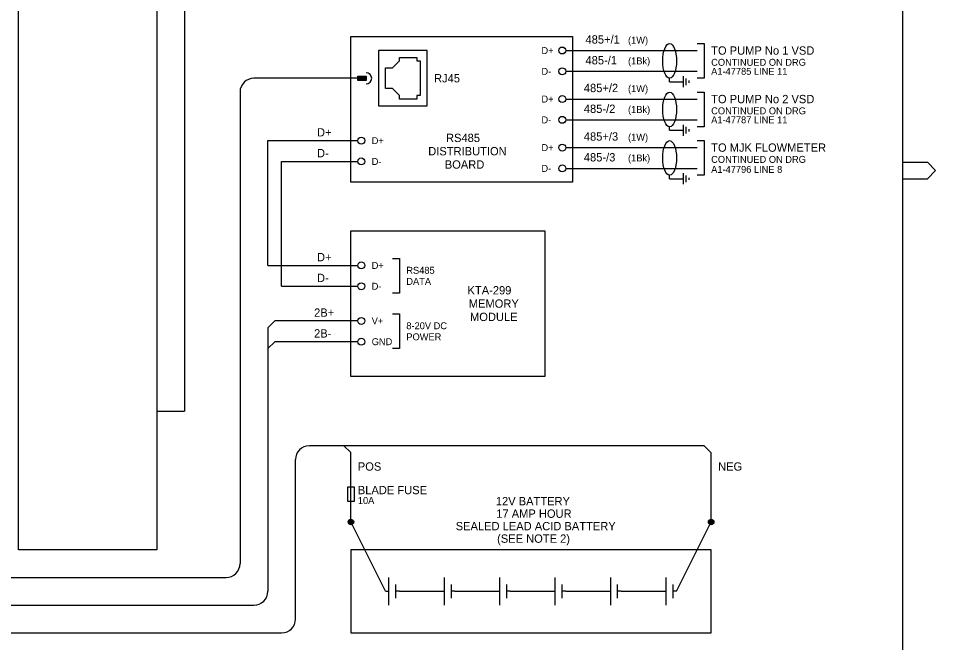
# Model space of a CAD drawing. Extents: x 0 to 841, y 0 to 594.
# Drawn here: x 510 to 841, y 126.5 to 351.6 of the extents above; entities that cross this region are included whole.
import ezdxf

# ---------------------------------------------------------------- set-up
doc = ezdxf.new("R2010")
doc.units = 0
for name, color, linetype in [('A1BORDER', 7, 'Continuous'), ('Level 1', 7, 'Continuous'), ('Level 10', 7, 'Continuous')]:
    doc.layers.add(name, color=color, linetype=linetype)

msp = doc.modelspace()

# ---------------------------------------------------------------- linework, layer by layer
at = {"layer": 'A1BORDER'}
for p, q in [((829, 581), (829, 15)), ((829, 299.76), (838, 299.76)), ((838, 299.76), (841, 296.76)), ((838, 293.76), (841, 296.76)), ((829, 293.76), (838, 293.76))]:
    msp.add_line(p, q, dxfattribs=at)
at = {"layer": 'Level 1'}
for p, q in [((570, 430), (570, 210)), ((707.5, 340), (755, 340)), ((647.5, 336.25), (645, 333.75)), ((647.5, 336.25), (647.5, 337.5)), ((647.5, 337.5), (653.75, 337.5)), ((653.75, 337.5), (653.75, 336.25)), ((653.75, 336.25), (655, 336.25)), ((655, 336.25), (655, 323.75)), ((642.5, 326.25), (642.5, 333.75)), ((642.5, 333.75), (645, 333.75)), ((707.5, 332.5), (755, 332.5)), ((632.5, 330), (595, 330)), ((745, 328.75), (745, 330)), ((745, 328.75), (750, 328.75)), ((590, 325), (590, 155)), ((645, 326.25), (642.5, 326.25)), ((647.5, 323.75), (645, 326.25)), ((647.5, 322.5), (647.5, 323.75)), ((653.75, 322.5), (647.5, 322.5)), ((655, 323.75), (653.75, 323.75)), ((653.75, 323.75), (653.75, 322.5)), ((707.5, 322.5), (755, 322.5)), ((707.5, 315), (755, 315)), ((745, 311.25), (745, 312.5)), ((745, 311.25), (750, 311.25)), ((600, 262.5), (600, 307.5)), ((600, 307.5), (632.5, 307.5)), ((707.5, 305), (755, 305)), ((605, 255), (605, 300)), ((605, 300), (632.5, 300)), ((707.5, 297.5), (755, 297.5)), ((745, 293.75), (745, 295)), ((745, 293.75), (750, 293.75)), ((600, 262.5), (632.5, 262.5)), ((605, 255), (632.5, 255)), ((602.5, 242.5), (600, 240)), ((632.5, 242.5), (602.5, 242.5)), ((600, 240), (600, 145)), ((602.5, 235), (600, 232.5)), ((632.5, 235), (602.5, 235)), ((560, 210), (570, 210)), ((757.5, 197.47), (615, 197.47)), ((630, 195), (627.5, 197.5)), ((757.5, 197.47), (760, 194.97)), ((610, 135), (610, 192.47)), ((630, 170), (630, 195)), ((760, 170), (760, 195)), ((642.5, 145), (630, 170)), ((747.5, 145), (760, 170)), ((385, 150), (585, 150)), ((647.5, 145), (662.5, 145)), ((667.5, 145), (682.5, 145)), ((687.5, 145), (702.5, 145)), ((707.5, 145), (722.5, 145)), ((727.5, 145), (742.5, 145)), ((275, 140), (595, 140)), ((265, 130), (605, 130))]:
    msp.add_line(p, q, dxfattribs=at)
for points in [[(510, 510), (560, 510), (560, 160), (510, 160)], [(630, 345), (710, 345), (710, 292.5), (630, 292.5)], [(657.5, 340), (640, 340), (640, 320), (657.5, 320)], [(630, 275), (700, 275), (700, 222.5), (630, 222.5)], [(760, 130), (760, 160), (630, 160), (630, 130)]]:
    msp.add_lwpolyline(points, close=True, dxfattribs=at)
for points in [[(755, 342.5), (757.5, 342.5), (757.5, 330), (755, 330)], [(755, 325), (757.5, 325), (757.5, 312.5), (755, 312.5)], [(755, 307.5), (757.5, 307.5), (757.5, 295), (755, 295)], [(645, 265), (647.5, 265), (647.5, 252.5), (645, 252.5)], [(645, 245), (647.5, 245), (647.5, 232.5), (645, 232.5)]]:
    msp.add_lwpolyline(points, dxfattribs=at)
for centre, start, end in [((595, 325), 90, 180), ((615, 192.47), 90, 180), ((585, 155), 270, 360), ((595, 145), 270, 360), ((605, 135), 270, 0)]:
    msp.add_arc(centre, 5, start, end, dxfattribs=at)
for centre in [(745, 336.25), (745, 318.75), (745, 301.25)]:
    msp.add_ellipse(centre, major_axis=(0, 6.25), ratio=0.4, dxfattribs=at)
at = {"layer": 'Level 10'}
for p, q in [((635.5, 330.48), (632.5, 330.48)), ((635.5, 330.18), (632.5, 330.18)), ((635.5, 329.88), (632.5, 329.88)), ((635.5, 329.58), (632.5, 329.58)), ((635.5, 329.28), (632.5, 329.28)), ((750, 326.75), (750, 330.75)), ((751, 327.55), (751, 329.95)), ((752, 328.35), (752, 329.15)), ((750, 309.25), (750, 313.25)), ((751, 310.05), (751, 312.45)), ((752, 310.85), (752, 311.65)), ((750, 291.75), (750, 295.75)), ((751, 292.55), (751, 294.95)), ((752, 293.35), (752, 294.15)), ((629, 170), (629, 170)), ((629.3, 169.29), (629.3, 170.71)), ((629.6, 169.08), (629.6, 170.92)), ((629.9, 169.01), (629.9, 170.99)), ((630.2, 169.02), (630.2, 170.98)), ((630.5, 169.13), (630.5, 170.87)), ((630.8, 169.4), (630.8, 170.6)), ((759, 170), (759, 170)), ((759.3, 169.29), (759.3, 170.71)), ((759.6, 169.08), (759.6, 170.92)), ((759.9, 169.01), (759.9, 170.99)), ((760.2, 169.02), (760.2, 170.98)), ((760.5, 169.13), (760.5, 170.87)), ((760.8, 169.4), (760.8, 170.6)), ((643.74, 140), (643.74, 150)), ((663.74, 140), (663.74, 150)), ((683.74, 140), (683.74, 150)), ((703.74, 140), (703.74, 150)), ((723.74, 140), (723.74, 150)), ((743.74, 140), (743.74, 150)), ((646.24, 142.5), (646.24, 147.5)), ((666.24, 142.5), (666.24, 147.5)), ((686.24, 142.5), (686.24, 147.5)), ((706.24, 142.5), (706.24, 147.5)), ((726.24, 142.5), (726.24, 147.5)), ((746.24, 142.5), (746.24, 147.5)), ((642.5, 145), (643.74, 145)), ((647.5, 145), (646.24, 145)), ((662.5, 145), (663.74, 145)), ((667.5, 145), (666.24, 145)), ((682.5, 145), (683.74, 145)), ((687.5, 145), (686.24, 145)), ((702.5, 145), (703.74, 145)), ((707.5, 145), (706.24, 145)), ((722.5, 145), (723.74, 145)), ((727.5, 145), (726.24, 145)), ((742.5, 145), (743.74, 145)), ((747.5, 145), (746.24, 145))]:
    msp.add_line(p, q, dxfattribs=at)
msp.add_lwpolyline([(635.5, 329.25), (632.5, 329.25), (632.5, 330.75), (635.5, 330.75)], close=True, dxfattribs=at)
msp.add_lwpolyline([(630, 177.5), (631.25, 177.5), (631.25, 182.5), (628.75, 182.5), (628.75, 177.5), (630, 177.5)], dxfattribs=at)
for centre, radius in [((706.25, 340), 1.25), ((706.25, 332.5), 1.25), ((706.25, 322.5), 1.25), ((706.25, 315), 1.25), ((633.75, 307.5), 1.25), ((706.25, 305), 1.25), ((633.75, 300), 1.25), ((706.25, 297.5), 1.25), ((633.75, 262.5), 1.25), ((633.75, 255), 1.25), ((633.75, 242.5), 1.25), ((633.75, 235), 1.25), ((630, 170), 1), ((760, 170), 1)]:
    msp.add_circle(centre, radius, dxfattribs=at)
msp.add_arc((635.5, 330), 2, 270, 90, dxfattribs=at)

# ---------------------------------------------------------------- texts
at = {"layer": 'Level 1'}
for s, height, p in [('485+/1', 3, (714.65, 342.5)), ('(1W)', 2.5, (730, 342.5)), ('D+', 2.5, (698.76, 338.75)), ('TO PUMP No 1 VSD', 3, (760, 338.5)), ('485-/1', 3, (714.65, 335)), ('(1Bk)', 2.5, (730, 335)), ('CONTINUED ON DRG', 2.5, (760, 334.5)), ('RJ45', 3, (660, 328.5)), ('D-', 2.5, (698.76, 331.25)), ('A1-47785 LINE 11', 2.5, (760, 331.25)), ('485+/2', 3, (714.05, 325)), ('(1W)', 2.5, (730, 325)), ('D+', 2.5, (698.76, 321.25)), ('TO PUMP No 2 VSD', 3, (760, 321)), ('485-/2', 3, (714.05, 317.5)), ('(1Bk)', 2.5, (730, 317.5)), ('CONTINUED ON DRG', 2.5, (760, 317)), ('D-', 2.5, (698.76, 313.75)), ('A1-47787 LINE 11', 2.5, (760, 313.75)), ('D+', 3, (617.76, 309)), ('D+', 2.5, (637.5, 306.25)), ('RS485', 3, (664.32, 307)), ('485+/3', 3, (714.05, 307.5)), ('(1W)', 2.5, (730, 307.5)), ('DISTRIBUTION', 3, (657.9, 302.2)), ('D+', 2.5, (698.76, 303.75)), ('TO MJK FLOWMETER', 3, (760, 303.5)), ('D-', 3, (617.76, 301.5)), ('D-', 2.5, (637.5, 298.75)), ('485-/3', 3, (714.05, 300)), ('(1Bk)', 2.5, (730, 300)), ('CONTINUED ON DRG', 2.5, (760, 299.5)), ('BOARD', 3, (663.87, 297.4)), ('D-', 2.5, (698.76, 296.25)), ('A1-47796 LINE 8', 2.5, (760, 295.88)), ('D+', 3, (617.76, 264)), ('D+', 2.5, (637.5, 261.25)), ('RS485', 2.5, (650, 259.5)), ('D-', 3, (617.76, 256.5)), ('D-', 2.5, (637.5, 253.75)), ('DATA', 2.5, (650, 255.5)), ('KTA-299', 3, (672.08, 252.05)), ('MEMORY', 3, (672.53, 247.25)), ('2B+', 3, (616.71, 244)), ('MODULE', 3, (672.98, 242.45)), ('V+', 2.5, (637.5, 241.25)), ('8-20V DC', 2.5, (650, 239.5)), ('2B-', 3, (616.71, 236.5)), ('GND', 2.5, (637.5, 233.75)), ('POWER', 2.5, (650, 235.5)), ('POS', 3, (632.5, 188.5)), ('NEG', 3, (762.5, 188.5)), ('BLADE FUSE', 3, (632.5, 180)), ('10A', 2.5, (632.5, 176.5)), ('12V BATTERY', 3, (682.3, 176)), ('17 AMP HOUR', 3, (682.45, 171.5)), ('SEALED LEAD ACID BATTERY', 3, (667.81, 167)), ('(SEE NOTE 2)', 3, (682.75, 162.5))]:
    msp.add_text(s, height=height, dxfattribs=at).set_placement(p)

doc.saveas('drawing.dxf')
